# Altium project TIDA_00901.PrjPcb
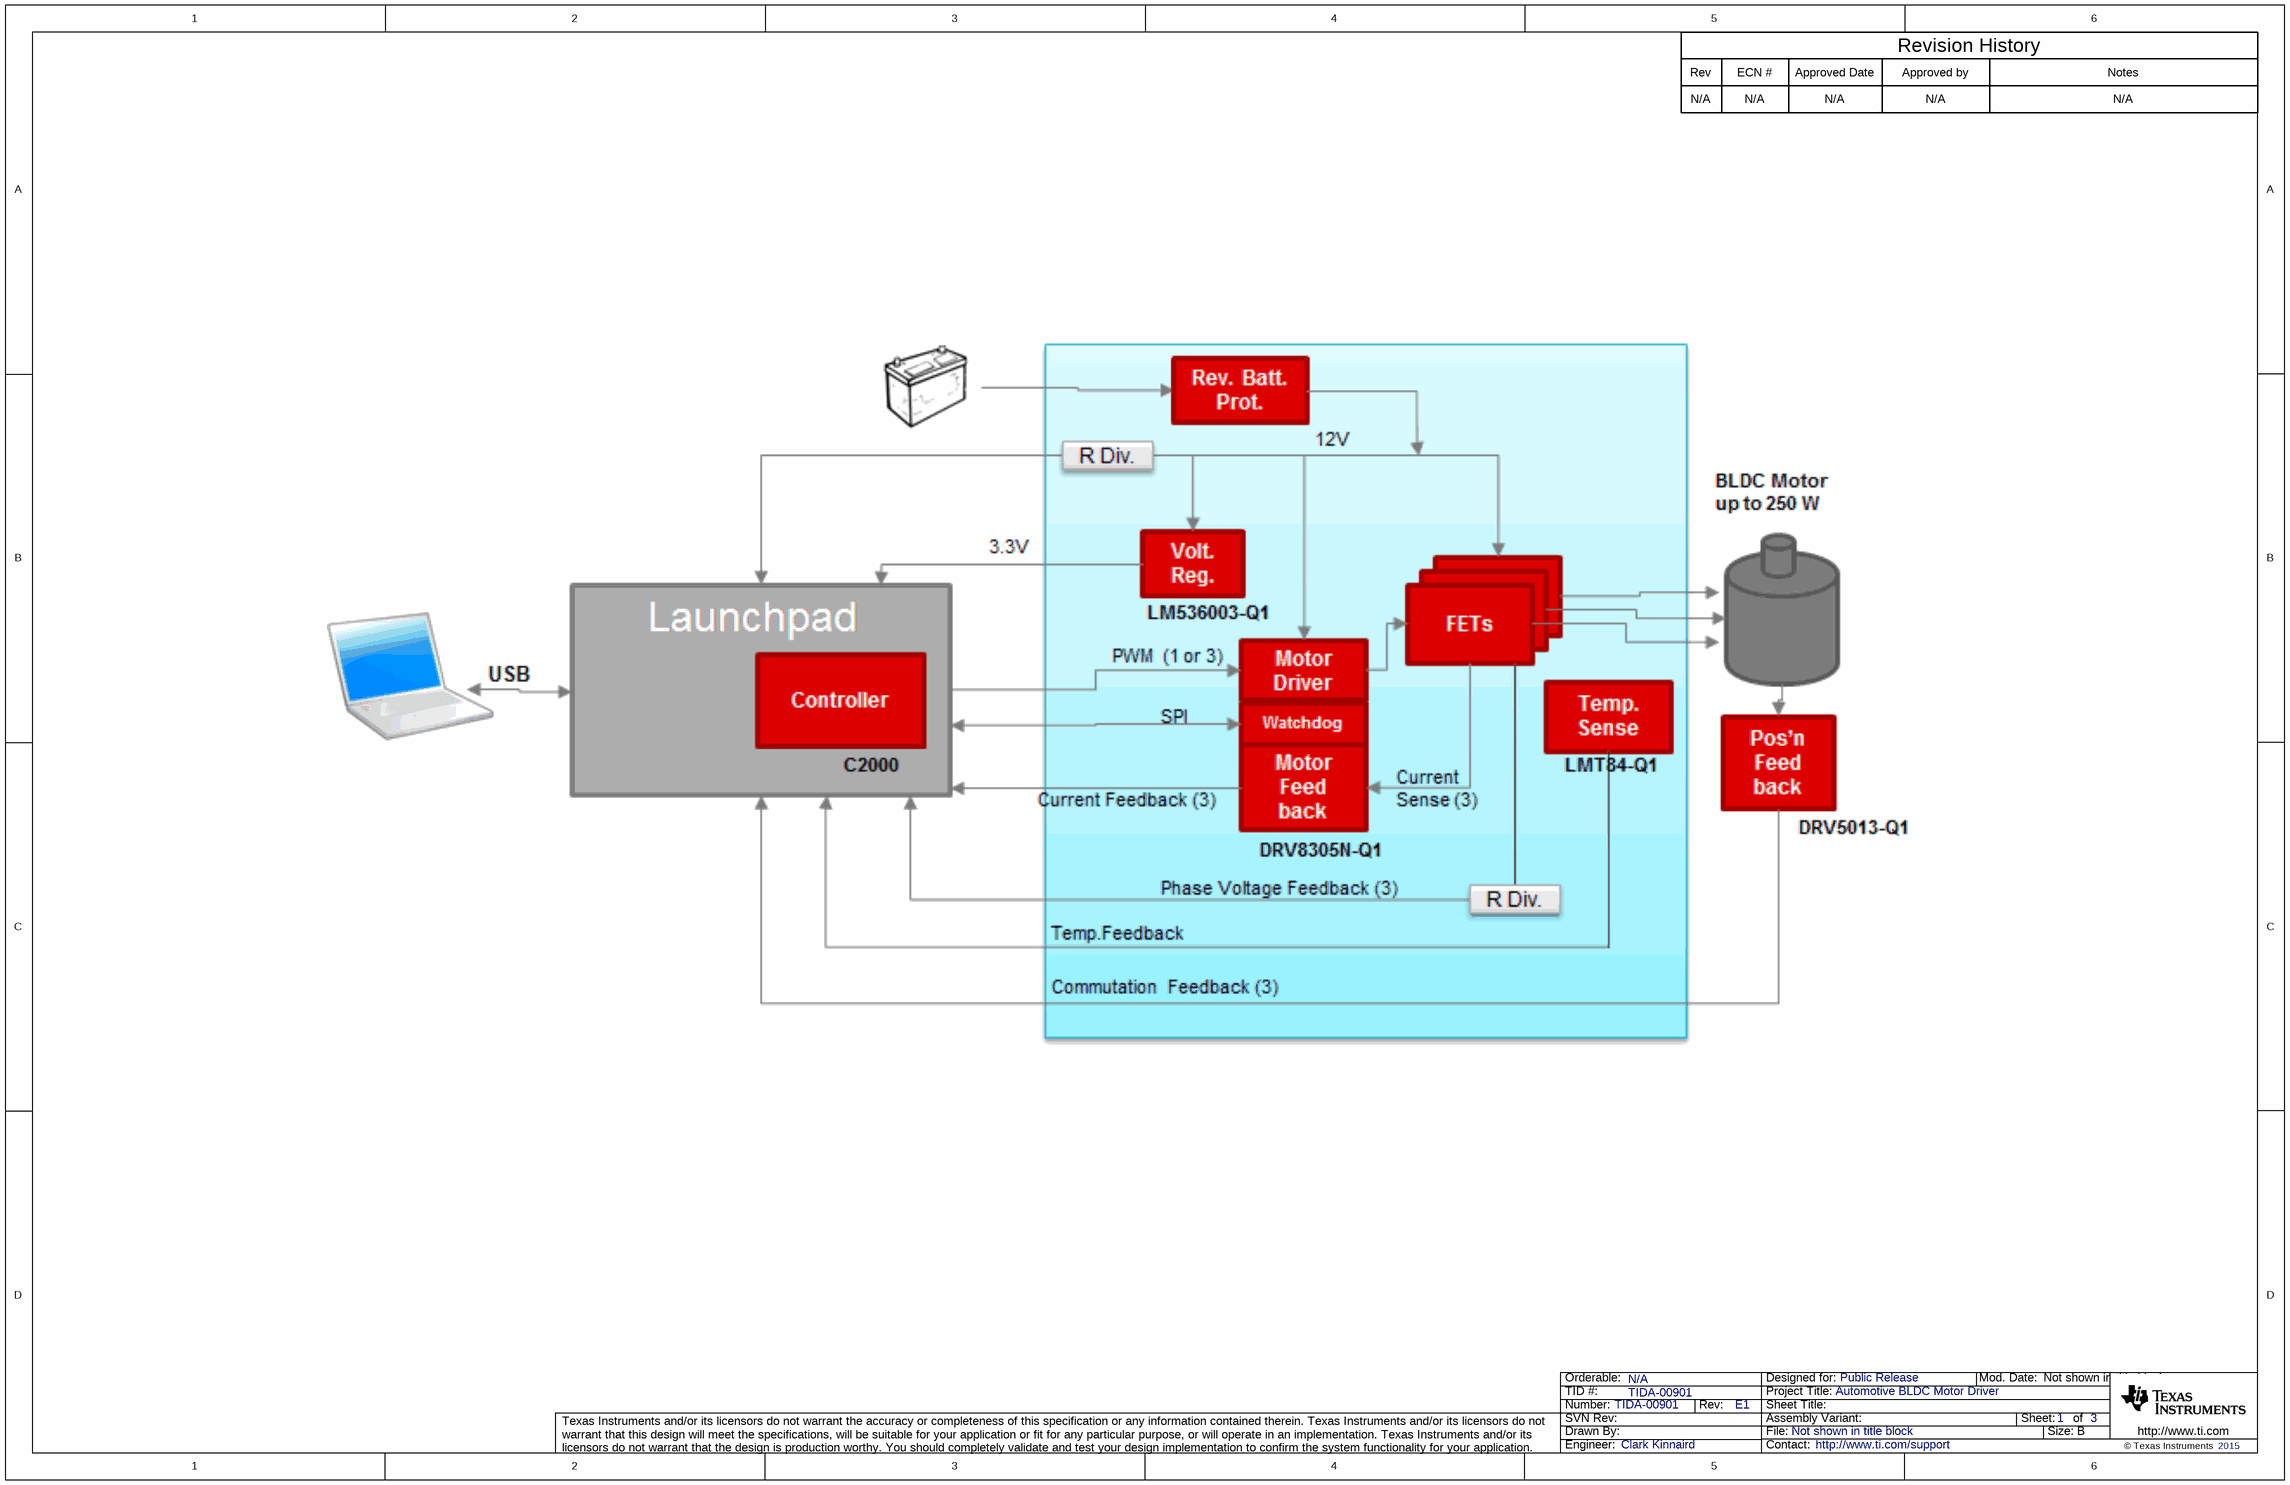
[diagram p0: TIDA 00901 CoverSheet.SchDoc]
CopyrightYear: 2015; EVM_Orderable: N/A; PCB_Layout: Krypton Solutions LLC; PCB_Rev: E1; PRJ_Customer: Public Release; PRJ_Engineer: Clark Kinnaird; PRJ_Number: TIDA-00901; PRJ_Title: Automotive BLDC Motor Driver; SCH_Rev: E1; TechSupport: http://www.ti.com/support; TID: TIDA-00901
3 sheets, 114 parts. Net scope: global (net labels, ports and power ports of the same name join across sheets).
Board file: TIDA_00901.PcbDoc
Sheets:
  TIDA 00901 CoverSheet.SchDoc
  TIDA 00901 Schematic 2.SchDoc
  TID_Hardware.SchDoc

## Sheet TIDA 00901 CoverSheet.SchDoc
size 431 x 279 mm; Date: Not shown in title block; ApprovedBy: Not shown in title block; CheckedBy: Not shown in title block; Author: Not shown in title block; CompanyName: Not shown in title block; Engineer: Not shown in title block; Organization: Not shown in title block; Address1: Not shown in title block; Address2: Not shown in title block; Address3: Not shown in title block; Address4: Not shown in title block; DocumentNumber: 1; Revision: Use project parameter SCH_Rev; SheetNumber: 1; SheetTotal: 3; PageSetup: Record=PageOptions¦CenterHorizontal=True¦CenterVertical=True¦PrintScale=1.00¦XCorrection=1.00¦YCorrection=1.00¦PrintKind=0¦BorderSize=5000000¦LeftOffset=0¦BottomOffset=0¦Orientation=2¦PaperLength=1000¦PaperWidth=1000¦Scale=100¦PaperSource=15¦PrintQuality=600¦MediaType=1¦DitherType=10¦PaperKind=Letter¦PrintScaleMode=1

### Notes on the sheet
- Rev
- N/A
- ECN #
- Approved Date
- Approved by
- Revision History
- Notes

## Sheet TIDA 00901 Schematic 2.SchDoc
size 431 x 279 mm; Date: Not shown in title block; ApprovedBy: Not shown in title block; CheckedBy: Not shown in title block; Author: Not shown in title block; CompanyName: Not shown in title block; Engineer: Not shown in title block; Organization: Not shown in title block; Address1: Not shown in title block; Address2: Not shown in title block; Address3: Not shown in title block; Address4: Not shown in title block; DocumentNumber: 1; Revision: Use project parameter SCH_Rev; SheetNumber: 2; SheetTotal: 2; PageSetup: Record=PageOptions¦CenterHorizontal=True¦CenterVertical=True¦PrintScale=0.96¦XCorrection=1.00¦YCorrection=1.00¦PrintKind=0¦BorderSize=5000000¦LeftOffset=0¦BottomOffset=0¦Orientation=2¦PaperLength=4318¦PaperWidth=2794¦Scale=100¦PaperSource=15¦PrintQuality=-3¦MediaType=1¦DitherType=10¦PrintScaleMode=1¦PaperKind=11x17¦PaperIndex=17
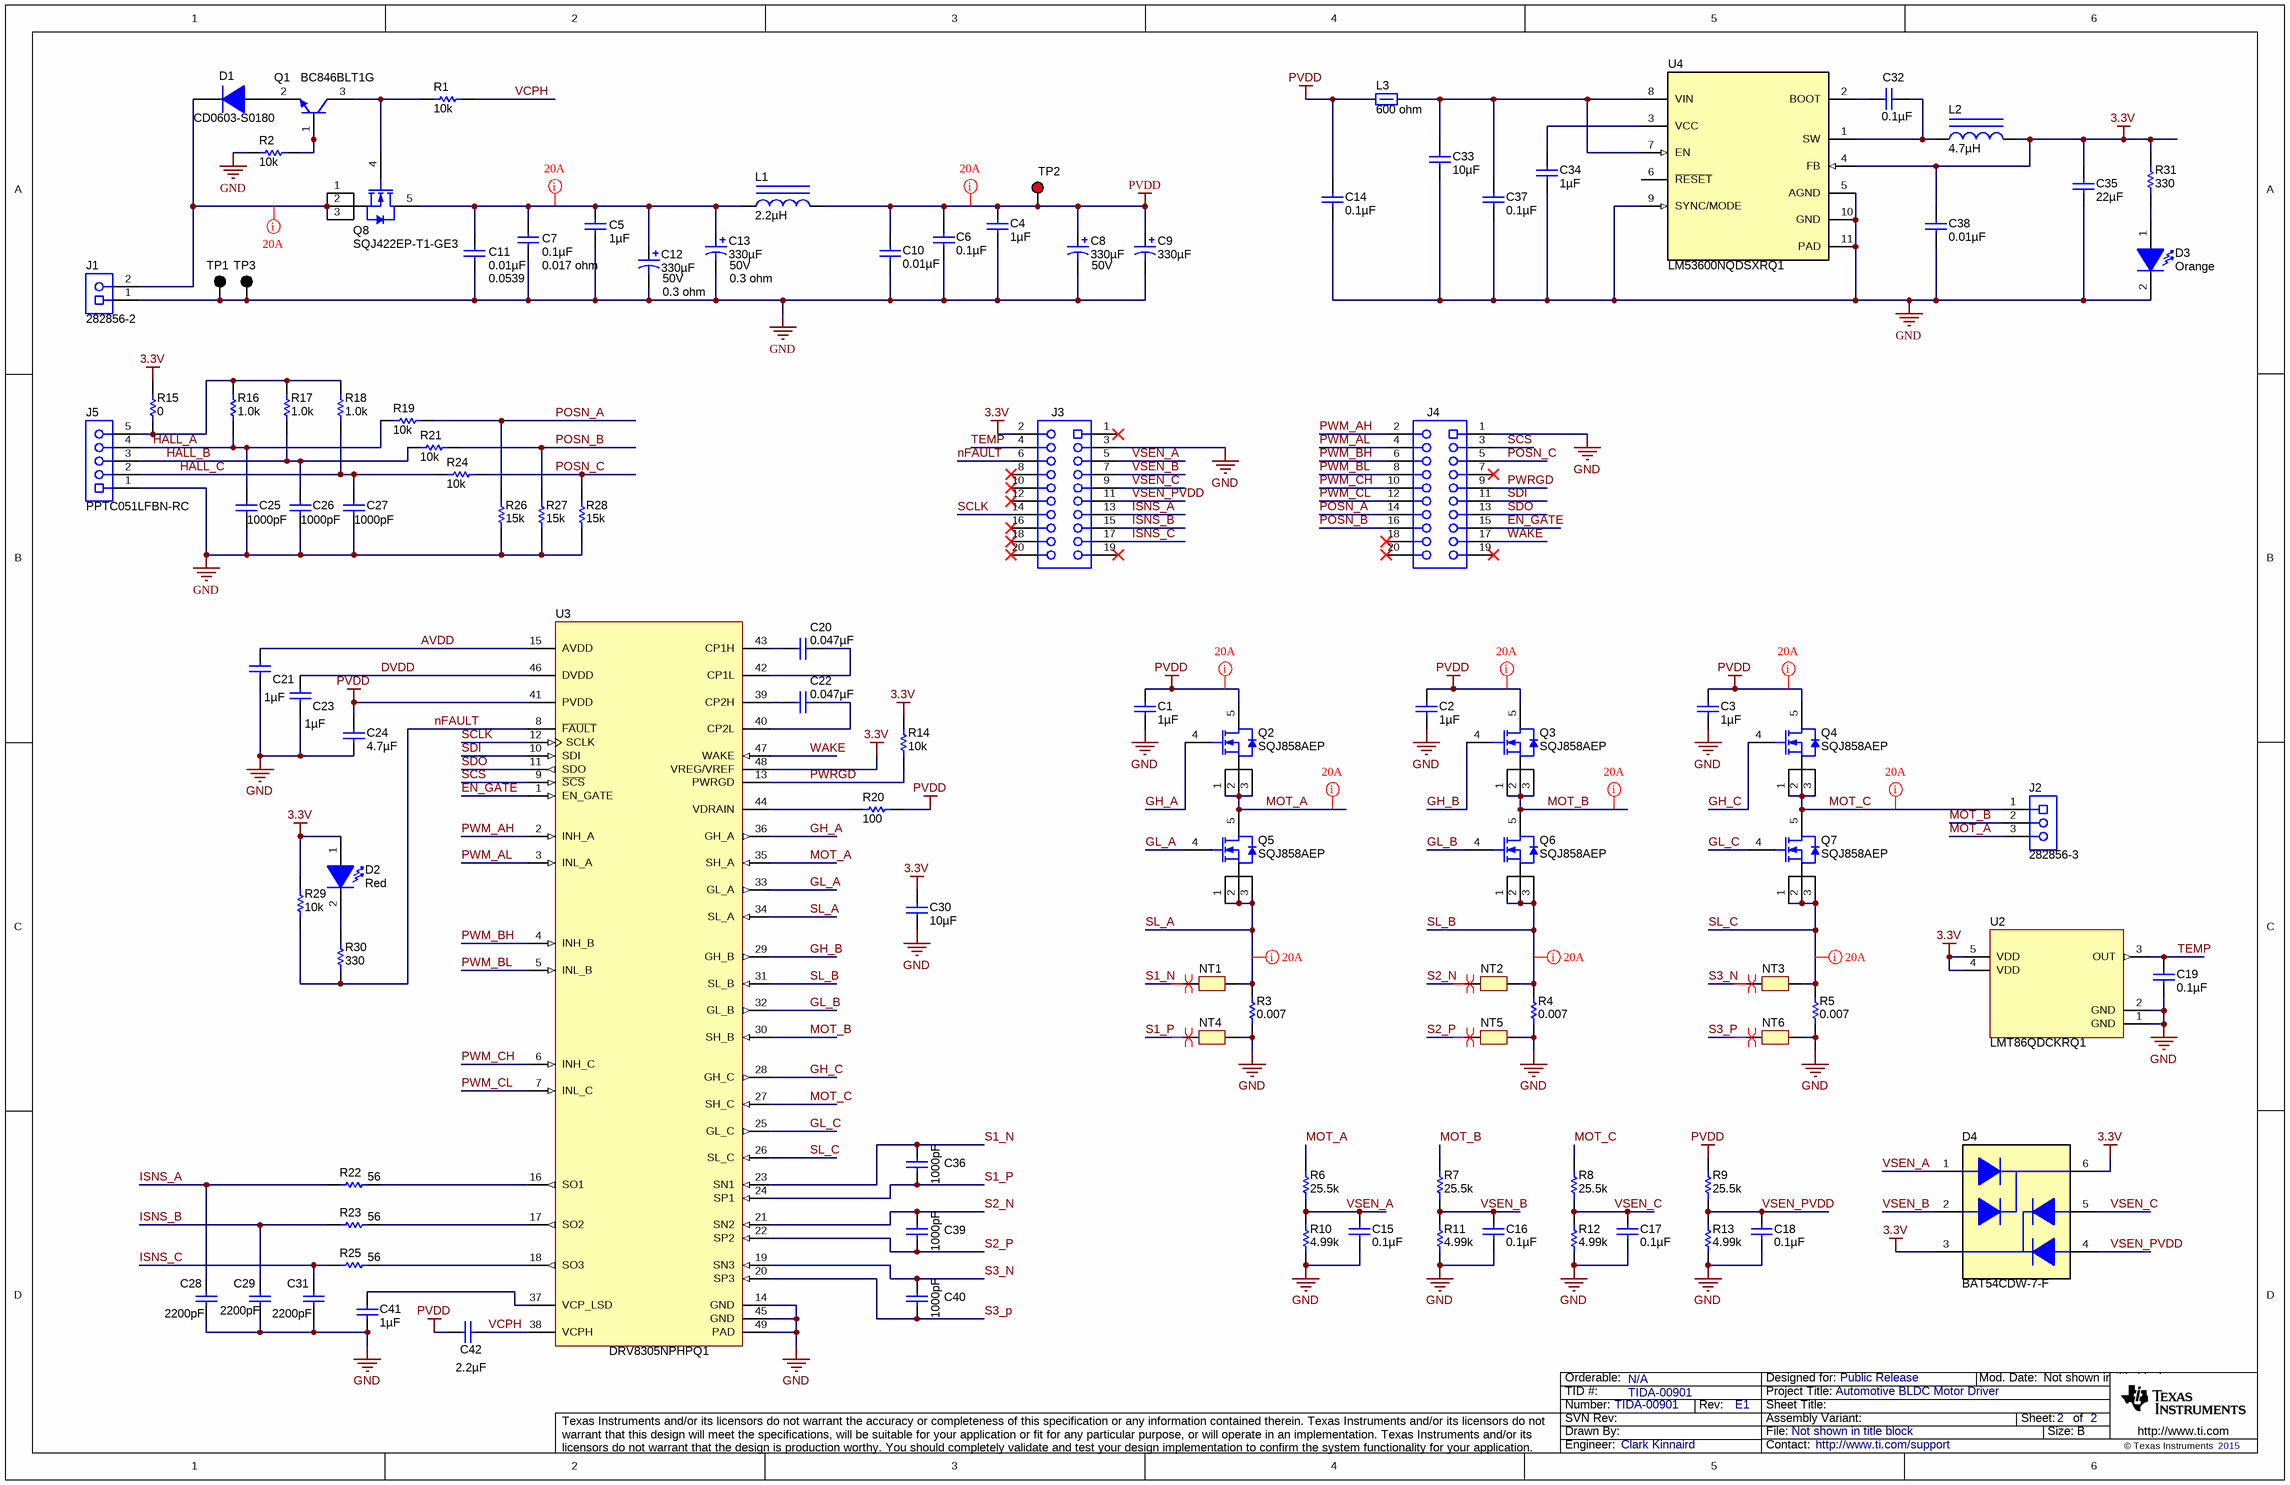
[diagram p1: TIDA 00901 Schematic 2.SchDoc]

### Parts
C1  ValueDisplayed: 1µF  [0603L]  (hidden comment: UMK107AB7105KA-T)
C2  ValueDisplayed: 1µF  [0603L]  (hidden comment: UMK107AB7105KA-T)
C3  ValueDisplayed: 1µF  [0603L]  (hidden comment: UMK107AB7105KA-T)
C4  ValueDisplayed: 1µF  [0805L]  (hidden comment: GRM21BR71H105KA12L)
C5  ValueDisplayed: 1µF  [0805L]  (hidden comment: GRM21BR71H105KA12L)
C6  ValueDisplayed: 0.1µF  [0603L]  (hidden comment: C1608X7R1H104K)
C7  ValueDisplayed: 0.1µF  Value1: 0.017 ohm  [0603L]  (hidden comment: C1608X7R1H104K)
C8  ValueDisplayed: 330µF  Value2: 50V  [SM_RADIAL_G]  (hidden comment: EEE-FT1H331AP)
C9  ValueDisplayed: 330µF  [SM_RADIAL_G]  (hidden comment: EEE-FT1H331AP)
C10  ValueDisplayed: 0.01µF  [0603L]  (hidden comment: C1608X7R1H103K)
C11  ValueDisplayed: 0.01µF  ESR_Ohm: 0.0539  [0603L]  (hidden comment: C1608X7R1H103K)
C12  ValueDisplayed: 330µF  Value1: 0.3 ohm  Value2: 50V  [SM_RADIAL_G]  (hidden comment: EEE-FT1H331AP)
C13  ValueDisplayed: 330µF  Value1: 0.3 ohm  Value2: 50V  [SM_RADIAL_G]  (hidden comment: EEE-FT1H331AP)
C14  ValueDisplayed: 0.1µF  [0603]  (hidden comment: GRM188R71H104KA93D)
C15  ValueDisplayed: 0.1µF  [0603L]  (hidden comment: C0603C104J4RACTU)
C16  ValueDisplayed: 0.1µF  [0603L]  (hidden comment: C0603C104J4RACTU)
C17  ValueDisplayed: 0.1µF  [0603L]  (hidden comment: C0603C104J4RACTU)
C18  ValueDisplayed: 0.1µF  [0603L]  (hidden comment: C0603C104J4RACTU)
C19  ValueDisplayed: 0.1µF  [0402]  (hidden comment: C0402C104K4RACAUTO)
C20  ValueDisplayed: 0.047µF  [0603L]  (hidden comment: C0603C473K1RACTU)
C21  ValueDisplayed: 1µF  [0603L]  (hidden comment: C1608X7R1C105K)
C22  ValueDisplayed: 0.047µF  [0603L]  (hidden comment: C0603C473K1RACTU)
C23  ValueDisplayed: 1µF  [0603L]  (hidden comment: C1608X7R1C105K)
C24  ValueDisplayed: 4.7µF  [1206L]  (hidden comment: GRM31CR71H475KA12L)
C25  ValueDisplayed: 1000pF  [0603L]  (hidden comment: GRM188R71C102KA01D)
C26  ValueDisplayed: 1000pF  [0603L]  (hidden comment: GRM188R71C102KA01D)
C27  ValueDisplayed: 1000pF  [0603L]  (hidden comment: GRM188R71C102KA01D)
C28  ValueDisplayed: 2200pF  [0603L]  (hidden comment: GRM188R71C222KA01D)
C29  ValueDisplayed: 2200pF  [0603L]  (hidden comment: GRM188R71C222KA01D)
C30  ValueDisplayed: 10µF  [0805_HV]  (hidden comment: C2012X7R1A106M125AC)
C31  ValueDisplayed: 2200pF  [0603L]  (hidden comment: GRM188R71C222KA01D)
C32  ValueDisplayed: 0.1µF  [0603]  (hidden comment: GRM188R71H104KA93D)
C33  ValueDisplayed: 10µF  [1210_280]  (hidden comment: C3225X7R1H106M250AC)
C34  ValueDisplayed: 1µF  [0603]  (hidden comment: GRM188R71C105KA12D)
C35  ValueDisplayed: 22µF  [1206]  (hidden comment: GRM31CR71A226KE15L)
C36  ValueDisplayed: 1000pF  [0603L]  (hidden comment: GRM188R71C102KA01D)
C37  ValueDisplayed: 0.1µF  [0603]  (hidden comment: GRM188R71H104KA93D)
C38  ValueDisplayed: 0.01µF  [0201]  (hidden comment: GRM033R71A103KA01D)
C39  ValueDisplayed: 1000pF  [0603L]  (hidden comment: GRM188R71C102KA01D)
C40  ValueDisplayed: 1000pF  [0603L]  (hidden comment: GRM188R71C102KA01D)
C41  ValueDisplayed: 1µF  [0603L]  (hidden comment: C1608X7R1C105K)
C42  ValueDisplayed: 2.2µF  [1210L]  (hidden comment: GRM32ER72A225KA35L)
D1  CD0603-S0180  [Diode_0603]
D2  value Red  [LED_LTST-C170]  (hidden comment: LTST-C170KRKT)
D3  value Orange  [LED_LTST-C190]  (hidden comment: LTST-C190KFKT)
D4  BAT54CDW-7-F  [SOT-363]
J1  282856-2  [TE_282856-2]
J2  282856-3  [TE_282856-3]
J3  CRD-081413-A-G  [Major_CRD-081413-A-x]  (value not drawn)
J4  CRD-081413-A-G  [Major_CRD-081413-A-x]  (value not drawn)
J5  PPTC051LFBN-RC  [Sullins_PPTC051LFBN-RC]
L1  ValueDisplayed: 2.2µH  [XAL1010]  (hidden comment: XAL1010-222MEB)
L2  ValueDisplayed: 4.7µH  [SPM3012]  (hidden comment: SPM3012T-4R7M)
L3  value 600 ohm  [0402]  (hidden comment: BLM15AX601SN1D)
NT1  Net-Tie  [Net-Tie_10mil]  (value not drawn)  (net tie, no BOM)
NT2  Net-Tie  [Net-Tie_10mil]  (value not drawn)  (net tie, no BOM)
NT3  Net-Tie  [Net-Tie_10mil]  (value not drawn)  (net tie, no BOM)
NT4  Net-Tie  [Net-Tie_10mil]  (value not drawn)  (net tie, no BOM)
NT5  Net-Tie  [Net-Tie_10mil]  (value not drawn)  (net tie, no BOM)
NT6  Net-Tie  [Net-Tie_10mil]  (value not drawn)  (net tie, no BOM)
Q1  BC846BLT1G  [SOT-23]
Q2  SQJ858AEP  [PowerPAK_SO-8L]
Q3  SQJ858AEP  [PowerPAK_SO-8L]
Q4  SQJ858AEP  [PowerPAK_SO-8L]
Q5  SQJ858AEP  [PowerPAK_SO-8L]
Q6  SQJ858AEP  [PowerPAK_SO-8L]
Q7  SQJ858AEP  [PowerPAK_SO-8L]
Q8  SQJ422EP-T1-GE3  [PowerPAK_SO-8L]
R1  ValueDisplayed: 10k  [0402]  (hidden comment: CRCW040210K0JNED)
R2  ValueDisplayed: 10k  [0402]  (hidden comment: CRCW040210K0JNED)
R3  ValueDisplayed: 0.007  [2512L]  (hidden comment: CRE2512-FZ-R007E-3)
R4  ValueDisplayed: 0.007  [2512L]  (hidden comment: CRE2512-FZ-R007E-3)
R5  ValueDisplayed: 0.007  [2512L]  (hidden comment: CRE2512-FZ-R007E-3)
R6  ValueDisplayed: 25.5k  [0402]  (hidden comment: CRCW040225K5FKED)
R7  ValueDisplayed: 25.5k  [0402]  (hidden comment: CRCW040225K5FKED)
R8  ValueDisplayed: 25.5k  [0402]  (hidden comment: CRCW040225K5FKED)
R9  ValueDisplayed: 25.5k  [0402]  (hidden comment: CRCW040225K5FKED)
R10  ValueDisplayed: 4.99k  [0402]  (hidden comment: CRCW04024K99FKED)
R11  ValueDisplayed: 4.99k  [0402]  (hidden comment: CRCW04024K99FKED)
R12  ValueDisplayed: 4.99k  [0402]  (hidden comment: CRCW04024K99FKED)
R13  ValueDisplayed: 4.99k  [0402]  (hidden comment: CRCW04024K99FKED)
R14  ValueDisplayed: 10k  [0402]  (hidden comment: CRCW040210K0JNED)
R15  ValueDisplayed: 0  [0402]  (hidden comment: ERJ-2GE0R00X)
R16  ValueDisplayed: 1.0k  [0402]  (hidden comment: CRCW04021K00JNED)
R17  ValueDisplayed: 1.0k  [0402]  (hidden comment: CRCW04021K00JNED)
R18  ValueDisplayed: 1.0k  [0402]  (hidden comment: CRCW04021K00JNED)
R19  ValueDisplayed: 10k  [0402]  (hidden comment: CRCW040210K0JNED)
R20  ValueDisplayed: 100  [0402]  (hidden comment: CRCW0402100RFKED)
R21  ValueDisplayed: 10k  [0402]  (hidden comment: CRCW040210K0JNED)
R22  ValueDisplayed: 56  [0402]  (hidden comment: CRCW040256R0JNED)
R23  ValueDisplayed: 56  [0402]  (hidden comment: CRCW040256R0JNED)
R24  ValueDisplayed: 10k  [0402]  (hidden comment: CRCW040210K0JNED)
R25  ValueDisplayed: 56  [0402]  (hidden comment: CRCW040256R0JNED)
R26  ValueDisplayed: 15k  [0402]  (hidden comment: CRCW040215K0JNED)
R27  ValueDisplayed: 15k  [0402]  (hidden comment: CRCW040215K0JNED)
R28  ValueDisplayed: 15k  [0402]  (hidden comment: CRCW040215K0JNED)
R29  ValueDisplayed: 10k  [0402]  (hidden comment: CRCW040210K0JNED)
R30  ValueDisplayed: 330  [0402]  (hidden comment: CRCW0402330RJNED)
R31  ValueDisplayed: 330  [0402]  (hidden comment: CRCW0402330RJNED)
TP1  5006  [Keystone5006]  (value not drawn)
TP2  5005  [Keystone5005]  (value not drawn)
TP3  5006  [Keystone5006]  (value not drawn)
U2  LMT86QDCKRQ1  [DCK0005A_N]
U3  DRV8305NPHPQ1  [PHP0048G_L]
U4  LM53600NQDSXRQ1  [DSX0010A]

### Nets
3.3V: C30.1 C35.1 C38.1 D2.1(A) D4.3(C2) D4.6(C1) J3.2 L2.2 R14.2 R15.2 R29.2 R31.2 U2.4(VDD) U2.5(VDD) U3.48(VREG/VREF) U4.4(FB)
GND: C1.2 C2.2 C3.2 C4.2 C5.2 C6.2 C7.2 C8.2(-) C9.2(-) C10.2 C11.2 C12.2(-) C13.2(-) C14.2 C15.2 C16.2 C17.2 C18.2 C19.2 C21.1 C23.1 C24.1 C25.2 C26.2 C27.2 C28.2 C29.2 C30.2 C31.2 C33.2 C34.2 C35.2 C37.2 C38.2 C41.2 D3.2(K) J1.1 J3.3 J4.1 J5.1 NT4.2 NT5.2 NT6.2 R2.2 R3.1 R4.1 R5.1 R10.1 R11.1 R12.1 R13.1 R26.1 R27.1 R28.1 TP1.1 TP3.1 U2.1(GND) U2.2(GND) U3.14(GND) U3.45(GND) U3.49(PAD) U4.5(AGND) U4.9(SYNC/MODE) U4.10(GND) U4.11(PAD)
PVDD: C1.1 C2.1 C3.1 C4.1 C6.1 C8.1(+) C9.1(+) C10.1 C14.1 C24.2 C42.2 L1.2 L3.1 Q2.5(D) Q3.5(D) Q4.5(D) R9.2 R20.2 TP2.1 U3.41(PVDD)
AVDD: C21.2 U3.15(AVDD)
DVDD: C23.2 U3.46(DVDD)
EN_GATE: J4.15 U3.1(EN_GATE)
GH_A: Q2.4(G) U3.36(GH_A)
GH_B: Q3.4(G) U3.29(GH_B)
GH_C: Q4.4(G) U3.28(GH_C)
GL_A: Q5.4(G) U3.33(GL_A)
GL_B: Q6.4(G) U3.32(GL_B)
GL_C: Q7.4(G) U3.25(GL_C)
HALL_A: C25.1 J5.4 R16.1 R19.1
HALL_B: C26.1 J5.3 R17.1 R21.1
HALL_C: C27.1 J5.2 R18.1 R24.1
ISNS_A: C28.1 J3.13 R22.1
ISNS_B: C29.1 J3.15 R23.1
ISNS_C: C31.1 J3.17 R25.1
MOT_A: J2.3 Q2.1(S) Q2.2(S) Q2.3(S) Q5.5(D) R6.2 U3.35(SH_A)
MOT_B: J2.2 Q3.1(S) Q3.2(S) Q3.3(S) Q6.5(D) R7.2 U3.30(SH_B)
MOT_C: J2.1 Q4.1(S) Q4.2(S) Q4.3(S) Q7.5(D) R8.2 U3.27(SH_C)
nFAULT: J3.6 R29.1 R30.1 U3.8(~{FAULT})
POSN_A: J4.14 R19.2 R26.2
POSN_B: J4.16 R21.2 R27.2
POSN_C: J4.5 R24.2 R28.2
PWM_AH: J4.2 U3.2(INH_A)
PWM_AL: J4.4 U3.3(INL_A)
PWM_BH: J4.6 U3.4(INH_B)
PWM_BL: J4.8 U3.5(INL_B)
PWM_CH: J4.10 U3.6(INH_C)
PWM_CL: J4.12 U3.7(INL_C)
PWRGD: J4.9 R14.1 U3.13(PWRGD)
S1_N: C36.1 NT1.1 U3.23(SN1)
S1_P: C36.2 NT4.1 U3.24(SP1)
S2_N: C39.1 NT2.1 U3.21(SN2)
S2_P: C39.2 NT5.1 U3.22(SP2)
S3_N: C40.1 NT3.1 U3.19(SN3)
S3_p: C40.2 NT6.1 U3.20(SP3)
SCLK: J3.14 U3.12(SCLK)
SCS: J4.3 U3.9(~{SCS})
SDI: J4.11 U3.10(SDI)
SDO: J4.13 U3.11(SDO)
SL_A: NT1.2 Q5.1(S) Q5.2(S) Q5.3(S) R3.2 U3.34(SL_A)
SL_B: NT2.2 Q6.1(S) Q6.2(S) Q6.3(S) R4.2 U3.31(SL_B)
SL_C: NT3.2 Q7.1(S) Q7.2(S) Q7.3(S) R5.2 U3.26(SL_C)
TEMP: C19.1 J3.4 U2.3(OUT)
VCPH: C42.1 R1.1 U3.38(VCPH)
VSEN_A: C15.1 D4.1(A1) J3.5 R6.1 R10.2
VSEN_B: C16.1 D4.2(A1) J3.7 R7.1 R11.2
VSEN_C: C17.1 D4.5(A2) J3.9 R8.1 R12.2
VSEN_PVDD: C18.1 D4.4(A2) J3.11 R9.1 R13.2
WAKE: J4.17 U3.47(WAKE)
NetC5_1: C5.1 C7.1 C11.1 C12.1(+) C13.1(+) L1.1 Q8.5(D)
NetC20_1: C20.1 U3.43(CP1H)
NetC20_2: C20.2 U3.42(CP1L)
NetC22_1: C22.1 U3.39(CP2H)
NetC22_2: C22.2 U3.40(CP2L)
NetC32_1: C32.1 U4.2(BOOT)
NetC32_2: C32.2 L2.1 U4.1(SW)
NetC33_1: C33.1 C37.1 L3.2 U4.7(EN) U4.8(VIN)
NetC34_1: C34.1 U4.3(VCC)
NetC41_1: C41.1 U3.37(VCP_LSD)
NetD1_1: D1.1(K) J1.2 Q8.1(S) Q8.2(S) Q8.3(S)
NetD1_2: D1.2(A) Q1.2(E)
NetD2_2: D2.2(K) R30.2
NetD3_1: D3.1(A) R31.1
NetJ5_5: J5.5 R15.1 R16.2 R17.2 R18.2
NetQ1_1: Q1.1(B) R2.1
NetQ1_3: Q1.3(C) Q8.4(G) R1.2
NetR20_1: R20.1 U3.44(VDRAIN)
NetR22_2: R22.2 U3.16(SO1)
NetR23_2: R23.2 U3.17(SO2)
NetR25_2: R25.2 U3.18(SO3)

Not connected (* = marked no-connect by the designer): J3 1* 8* 10* 12* 16* 18* 19* 20*; J4 7* 18* 19* 20*; U4 6(~{RESET})

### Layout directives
rule Undefined: MOT_A, MOT_B, MOT_C, NetC5_1, NetD1_1, PVDD, SL_A, SL_B, SL_C
differential pair: S1_N, S1_P, S2_N, S2_P, S3_N, S3_p

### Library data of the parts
C1-C3 = UMK107AB7105KA-T: CAP, CERM, 1 µF, 50 V, +/- 10%, X7R, 0603; Manufacturer: Taiyo Yuden; Polarized: N; CompType: Capacitor; Value: 1uF; U/M: EA; Cap_F: 0.000001; Tolerance_%: 10; Value1: Unknown; VDC_V: 50; Value2: 50V; TaMin_C: -55; TaMax_C: 125; Cap_Case: 0603
C4 C5 = GRM21BR71H105KA12L: CAP, CERM, 1uF, 50V, +/-10%, X7R, 0805; Manufacturer: MuRata; Polarized: N; CompType: Capacitor; U/M: EA; Cap_F: 0.000001; Tolerance_%: 10; Value1: Unknown; VDC_V: 50; TaMin_C: -55; TaMax_C: 125; Cap_Case: 0805
C6 = C1608X7R1H104K: CAP, CERM, 0.1uF, 50V, +/-10%, X7R, 0603; Manufacturer: TDK; Polarized: N; CompType: Capacitor; U/M: EA; Cap_F: 0.0000001; Tolerance_%: 10; ESR_Ohm: 0.017; Value1: 0.017 ohm; VDC_V: 50; TaMin_C: -55; TaMax_C: 125; Cap_Case: 0603
C7 = C1608X7R1H104K: CAP, CERM, 0.1uF, 50V, +/-10%, X7R, 0603; Manufacturer: TDK; Polarized: N; CompType: Capacitor; U/M: EA; Cap_F: 0.0000001; Tolerance_%: 10; ESR_Ohm: 0.017; VDC_V: 50; TaMin_C: -55; TaMax_C: 125; Cap_Case: 0603
C8 = EEE-FC1H221P: CAP, AL, 330 µF, 50 V, +/- 20%, 0.3 ohm, SMD; Manufacturer: Panasonic; Polarized: Y; CompType: Capacitor; Value: 330uF; U/M: EA; Cap_F: 0.00033; Tolerance_%: 20; Value1: 0.3 ohm; VDC_V: 50; ESR_ohm: 0.3; IRMS_A: 0.5; TaMin_C: -40; TaMax_C: 105; Cap_Case: G
C9 = EEE-FC1H221P: CAP, AL, 330 µF, 50 V, +/- 20%, 0.3 ohm, SMD; Manufacturer: Panasonic; Polarized: Y; CompType: Capacitor; Value: 330uF; U/M: EA; Cap_F: 0.00033; Tolerance_%: 20; Value1: 0.3 ohm; VDC_V: 50; Value2: 50V; ESR_ohm: 0.3; IRMS_A: 0.5; TaMin_C: -40; TaMax_C: 105; Cap_Case: G
C10 = C1608X7R1H103K: CAP, CERM, 0.01uF, 50V, +/-10%, X7R, 0603; Manufacturer: TDK; Polarized: N; CompType: Capacitor; U/M: EA; Cap_F: 0.00000001; Tolerance_%: 10; ESR_Ohm: 0.0539; Value1: 0.0539 ohm; VDC_V: 50; TaMin_C: -55; TaMax_C: 125; Cap_Case: 0603
C11 = C1608X7R1H103K: CAP, CERM, 0.01uF, 50V, +/-10%, X7R, 0603; Manufacturer: TDK; Polarized: N; CompType: Capacitor; U/M: EA; Cap_F: 0.00000001; Tolerance_%: 10; Value1: 0.0539 ohm; VDC_V: 50; TaMin_C: -55; TaMax_C: 125; Cap_Case: 0603
C12 C13 = EEE-FC1H221P: CAP, AL, 330 µF, 50 V, +/- 20%, 0.3 ohm, SMD; Manufacturer: Panasonic; Polarized: Y; CompType: Capacitor; Value: 330uF; U/M: EA; Cap_F: 0.00033; Tolerance_%: 20; VDC_V: 50; ESR_ohm: 0.3; IRMS_A: 0.5; TaMin_C: -40; TaMax_C: 105; Cap_Case: G
C14 C32 C37 = GRM188R71H104KA93D: CAP, CERM, 0.1 µF, 50 V, +/- 10%, X7R, 0603; Manufacturer: MuRata; Polarized: N; CompType: Capacitor; Value: 0.1uF; U/M: EA; Cap_F: 0.0000001; Tolerance_%: 10; Value1: Unknown; VDC_V: 50; Value2: 50V; TaMin_C: -55; TaMax_C: 125; AEC Category: Q200
C15-C18 = C0603C104J4RACTU: CAP, CERM, 0.1 µF, 16 V, +/- 5%, X7R, 0603; Manufacturer: Kemet; Polarized: N; CompType: Capacitor; Value: 0.1uF; U/M: EA; Cap_F: 0.0000001; Tolerance_%: 5; Value1: Unknown; VDC_V: 16; Value2: 16V; TaMin_C: -55; TaMax_C: 125; Cap_Case: 0603
C19 = C0402C104K4RACAUTO: CAP, CERM, 0.1 µF, 16 V, +/- 10%, X7R, AEC-Q200 Grade 1, 0402; Manufacturer: Kemet; Polarized: N; CompType: Capacitor; Value: 0.1uF; U/M: EA; Cap_F: 0.0000001; Tolerance_%: 10; Value1: Unknown; VDC_V: 16; Value2: 16V; TaMin_C: -55; TaMax_C: 125; AEC Category: Q200; AEC Qualified: Y; AEC Grade: 1
C20 C22 = GRM188R72A104KA35D: CAP, CERM, 0.047uF, 100V, +/-10%, X7R, 0603; Manufacturer: Kemet; Polarized: N; CompType: Capacitor; U/M: EA; Cap_F: 0.000000047; Tolerance_%: 10; Value1: Unknown; VDC_V: 100; TaMin_C: -55; TaMax_C: 125; Cap_Case: 0603
C21 C23 C41 = C1608X7R1C105K: CAP, CERM, 1 µF, 16 V, +/- 10%, X7R, 0603; Manufacturer: TDK; Polarized: N; CompType: Capacitor; Value: 1uF; U/M: EA; Cap_F: 0.000001; Tolerance_%: 10; ESR_ohm: 0.0057; Value1: 0.0057 ohm; VDC_V: 16; Value2: 16V; TaMin_C: -55; TaMax_C: 125; Cap_Case: 0603
C24 = GRM31CR71H475KA12L: CAP, CERM, 4.7 µF, 50 V, +/- 10%, X7R, 1206; Manufacturer: MuRata; Polarized: N; CompType: Capacitor; Value: 4.7uF; U/M: EA; Cap_F: 0.0000047; Tolerance_%: 10; Value1: Unknown; VDC_V: 50; Value2: 50V; TaMin_C: -55; TaMax_C: 125; Cap_Case: 2220
C25-C27 C36 C39 C40 = GRM188R71C102KA01D: CAP, CERM, 1000pF, 16V, +/-10%, X7R, 0603; Manufacturer: MuRata; Polarized: N; CompType: Capacitor; U/M: EA; Cap_F: 0.000000001; Tolerance_%: 10; Value1: Unknown; VDC_V: 16; TaMin_C: -55; TaMax_C: 125; Cap_Case: 0603
C28 C29 C31 = GRM188R71C222KA01D: CAP, CERM, 2200pF, 16V, +/-10%, X7R, 0603; Manufacturer: MuRata; Polarized: N; CompType: Capacitor; U/M: EA; Cap_F: 0.0000000022; Tolerance_%: 10; Value1: Unknown; VDC_V: 16; TaMin_C: -55; TaMax_C: 125; Cap_Case: 0603
C30 = C2012X7R1A106M125AC: CAP, CERM, 10 µF, 10 V, +/- 20%, X7R, 0805; Manufacturer: TDK; Polarized: N; CompType: Capacitor; Value: 10uF; U/M: EA; Cap_F: 0.00001; Tolerance_%: 20; Value1: Unknown; VDC_V: 10; Value2: 10V; TaMin_C: -55; TaMax_C: 125; Cap_Case: 0805; AEC Category: Q200
C33 = C3225X7R1H106M250AC: CAP, CERM, 10 µF, 50 V, +/- 20%, X7R, 1210; Manufacturer: TDK; Polarized: N; CompType: Capacitor; Value: 10uF; U/M: EA; Cap_F: 0.00001; Tolerance_%: 20; Value1: Unknown; VDC_V: 50; Value2: 50V; TaMin_C: -55; TaMax_C: 125; Cap_Case: 1210; AEC Category: Q200
C34 = GRM188R71C105KA12D: CAP, CERM, 1 µF, 16 V, +/- 10%, X7R, 0603; Manufacturer: MuRata; Polarized: N; CompType: Capacitor; Value: 1uF; U/M: EA; Cap_F: 0.000001; Tolerance_%: 10; ESR_ohm: 0.011; Value1: 0.011 ohm; VDC_V: 16; Value2: 16V; TaMin_C: -55; TaMax_C: 125; AEC Category: Q200
C35 = GRM31CR71A226KE15L: CAP, CERM, 22 µF, 10 V, +/- 10%, X7R, 1206; Manufacturer: MuRata; Polarized: N; CompType: Capacitor; Value: 22uF; U/M: EA; Cap_F: 0.000022; Tolerance_%: 10; Value1: Unknown; Value2: 10V; TaMin_C: -55; TaMax_C: 125; AEC Category: Q200
C38 = GRM033R71A103KA01D: CAP, CERM, 0.01 µF, 10 V, +/- 10%, X7R, 0201; Manufacturer: MuRata; Polarized: N; CompType: Capacitor; Value: 0.01uF; U/M: EA; Cap_F: 0.00000001; Tolerance_%: 10; Value1: Unknown; Value2: 10V; TaMin_C: -55; TaMax_C: 125; AEC Category: Q200
C42 = GRM32ER72A225KA35L: CAP, CERM, 2.2 µF, 100 V, +/- 10%, X7R, 1210; Manufacturer: MuRata; Polarized: N; CompType: Capacitor; Value: 2.2uF; U/M: EA; Cap_F: 0.0000022; Tolerance_%: 10; ESR_ohm: 0.007; Value1: 0.007 ohm; VDC_V: 100; Value2: 100V; IRMS_A: 4.4; TaMin_C: -55; TaMax_C: 125; Cap_Case: 1210
D1 = CD0603-S0180: Diode, Switching, 90V, 0.1A, 0603 Diode; Manufacturer: Bourns; U/M: EA; Vf_V: 1; Value2: 1V; Io_A: 0.1; Vr_V: 90; TJmax_C: 125
D2 = LTST-C170KRKT: LED, Red, SMD; Manufacturer: Lite-On; Type: AlInGaP; Vf_V: 2; Value2: 2V; Io_A: 20; Value1: W; U/M: EA
D3 = LTST-C190KFKT: LED, Orange, SMD; Manufacturer: Lite-On; Type: AlInGaP; Vf_V: 2; Value2: 2V; Io_A: 0.02; Power_TotalModule: 0.075; Value1: 0.075W; U/M: EA
D4 = BAT54CDW-7-F: Diode, Schottky, 30 V, 0.2 A, SOT-363; Manufacturer: Diodes Inc.; SymbolCreator: Altium; U/M: EA; Vf_V: 1; Value: 30V; Value1: 0.2A; Value2: 1V; Io_A: 0.2; Vr_V: 30; TJmax_C: 125; AEC Category: Q101; AEC Qualified: N
J1 = 282856-2: Therminal Block, 5 mm, 2-pole, Tin, TH; Manufacturer: TE Connectivity; SymbolCreator: a0412235; CompType: Terminal Block
J2 = 282856-3: Receptacle, 3x1, 5mm, R/A, TH; Manufacturer: TE Connectivity; SymbolCreator: a0412235; CompType: Terminal Block; Pitch_mm: 5; Gender: Female; Row_Count: 1; ContactFinish: Tin; Current_A: 24; Voltage_V: 300; Cert_UL: Y
J3 J4 = CRD-081413-A-G: Receptacle, 2.54 mm, 10x2, Gold, TH; Manufacturer: Major League Electronics; SymbolCreator: a0412235; U/M: EA
J5 = PPTC051LFBN-RC: Receptacle, 2.54 mm, 5x1, Tin, TH; Manufacturer: Sullins Connector Solutions; SymbolCreator: a0412235; U/M: EA
L1 = XAL1010-222MEB: Inductor, Shielded, Composite, 2.2 µH, 32 A, 0.00255 ohm, SMD; Manufacturer: Coilcraft; Value: 2.2uH; Ind_H: 2.2E-6; Imax_A: 32; Irms: 32A @ 40C rise; Isat: 34A @ 30% inductance drop; Value2: 32A; AEC Category: Q200
L2 = SPM3012T-4R7M: Inductor, Shielded, Ferrite, 4.7 µH, 1.5 A, 0.27 ohm, SMD; Manufacturer: TDK; Value: 4.7uH; Ind_H: 4.7E-6; Imax_A: 1.5; Irms: 1.5A @ 40C rise; Isat: 1.5A @ 30% inductance drop; DCR_ohm: 0.27; Value2: 1.5A; AEC Category: Q200
L3 = BLM15AX601SN1D: Ferrite Bead, 600 ohm @ 100 MHz, 0.5 A, 0402; Manufacturer: MuRata; Imax_A: 0.5; DCR_ohm: 0.34; Value1: 0.34 ohm; Value2: 0.5A; ZTyp@100MHz_Ohm: 600
NT1-NT6 = Net-Tie: Single point connection between nets.; SymbolCreator: codlsc
Q1 = BC846BLT1G, ON Semiconductor: Transistor, NPN, 65V, 0.1A, SOT-23; CompType: BJT; PNP: 0; NPN: 1; Vceo_V: 65; Vcesat1_V: 0.7; Value: 0.7V; IcRated_A: 0.1; HfeMax: 450; TaMin_C: -55; TaMax_C: 150; U/M: EA
Q2-Q7 = SQJ858AEP-T1-GE3: MOSFET, N-CH, 40 V, 58 A, PowerPAK_SO-8L; Manufacturer: Vishay-Siliconix; Alternate Manufacturer: None; SymbolCreator: a0412235; U/M: EA; ChType: N; Value: 40V; VdsMax_V: 40; Value1: 0.0075 ohm; Rdson45_ohm: 0.0075; Value2: 36 nC; QgTyp_nC: 36; Vgs_V: 20; IdsMax_A: 58; AEC Category: Q101
Q8 = SQJ422EP-T1-GE3: MOSFET, N-CH, 40 V, 75 A, PowerPAK_SO-8L; Manufacturer: Vishay-Siliconix; Alternate Manufacturer: None; SymbolCreator: a0412235; U/M: EA; ChType: N; Value: 40V; VdsMax_V: 40; Value1: 0.0043 ohm; Rdson45_ohm: 0.0043; Value2: 67 nC; QgTyp_nC: 67; Vgs_V: 20; IdsMax_A: 75; AEC Category: Q101
R1 R2 R14 R19 R21 R24 R29 = CRCW040210K0JNED: RES, 10 k, 5%, 0.063 W, 0402; Manufacturer: Vishay-Dale; CompType: Resistor; Value: 10k; Res_ohm: 10000; Value_Code: 10k0; Tolerance_%: 5; Power_W: 0.063; Value2: 0.063W; VDC_V: 50; TempCo: 200 ppm/C; EIA_Code: E24; U/M: EA; AEC Category: Q200
R3-R5 = PMR100HZPFU7L00: RES SMD 0.007 OHM 1% 3W 2512; Manufacturer: Bourns Inc.; CompType: Resistor; Value: 0.007; Value_Code: 7L000; Tolerance_%: 1; Power_W: 3; TempCo: 100 ppm/C; EIA_Code: E96; U/M: EA
R6-R9 = CRCW040225K5FKED: RES, 25.5 k, 1%, 0.063 W, 0402; Manufacturer: Vishay-Dale; CompType: Resistor; Value: 25.5k; Res_ohm: 25500; Value_Code: 25k5; Tolerance_%: 1; Power_W: 0.063; Value2: 0.063W; VDC_V: 50; TempCo: 100 ppm/C; EIA_Code: E96; U/M: EA; AEC Category: Q200
R10-R13 = CRCW04024K99FKED: RES, 4.99 k, 1%, 0.063 W, 0402; Manufacturer: Vishay-Dale; CompType: Resistor; Value: 4.99k; Res_ohm: 4990; Value_Code: 4k99; Tolerance_%: 1; Power_W: 0.063; Value2: 0.063W; VDC_V: 50; TempCo: 100 ppm/C; EIA_Code: E96; U/M: EA; AEC Category: Q200
R15 = ERJ-2GE0R00X: RES, 0, 5%, 0.063 W, 0402; Manufacturer: Panasonic; CompType: Resistor; Value: 0; Value_Code: 0000; Tolerance_%: 5; Power_W: 0.063; Value2: 0.063W; VDC_V: 50; TempCo: 600 ppm/C; EIA_Code: E24; U/M: EA; AEC Category: Q200
R16-R18 = CRCW04021K00JNED: RES, 1.0 k, 5%, 0.063 W, 0402; Manufacturer: Vishay-Dale; CompType: Resistor; Value: 1.0k; Res_ohm: 1000; Value_Code: 1k00; Tolerance_%: 5; Power_W: 0.063; Value2: 0.063W; VDC_V: 50; TempCo: 200 ppm/C; EIA_Code: E24; U/M: EA; AEC Category: Q200
R20 = CRCW0402100RFKED: RES, 100, 1%, 0.063 W, 0402; Manufacturer: Vishay-Dale; CompType: Resistor; Value: 100; Value_Code: 100R; Tolerance_%: 1; Power_W: 0.063; Value2: 0.063W; VDC_V: 50; TempCo: 100 ppm/C; EIA_Code: E96; U/M: EA; AEC Category: Q200
R22 R23 R25 = CRCW040256R0JNED: RES, 56, 5%, 0.063 W, 0402; Manufacturer: Vishay-Dale; CompType: Resistor; Value: 56; Value_Code: 56R0; Tolerance_%: 5; Power_W: 0.063; Value2: 0.063W; VDC_V: 50; TempCo: 200 ppm/C; EIA_Code: E24; U/M: EA; AEC Category: Q200
R26-R28 = CRCW040215K0JNED: RES, 15 k, 5%, 0.063 W, 0402; Manufacturer: Vishay-Dale; CompType: Resistor; Value: 15k; Res_ohm: 15000; Value_Code: 15k0; Tolerance_%: 5; Power_W: 0.063; Value2: 0.063W; VDC_V: 50; TempCo: 200 ppm/C; EIA_Code: E24; U/M: EA; AEC Category: Q200
R30 R31 = CRCW0402330RJNED: RES, 330, 5%, 0.063 W, 0402; Manufacturer: Vishay-Dale; CompType: Resistor; Value: 330; Value_Code: 330R; Tolerance_%: 5; Power_W: 0.063; Value2: 0.063W; VDC_V: 50; TempCo: 200 ppm/C; EIA_Code: E24; U/M: EA; AEC Category: Q200
TP1 TP3 = 5006: Test Point, Compact, Black, TH; Manufacturer: Keystone; CompType: Test Point Loop; U/M: EA
TP2 = 5005: Test Point, Compact, Red, TH; Manufacturer: Keystone; CompType: Test Point Loop; U/M: EA
U2 = LMT86QDCKRQ1: SC70 Analog Temperature Sensor with Class-AB Output, DCK0005A; Alternate PartNumber: LMT86QDCKTQ1; Manufacturer: Texas Instruments; SymbolCreator: a0799628; CompType: IC; U/M: EA
U3 = DRV83053EPHPRQ1: Three Phase Automotive Gate Driver with Three Integrated Current Shunt Amplifiers and Voltage Regulator, PHP0048G; Alternate PartNumber: DRV83053EPHPQ1; Manufacturer: Texas Instruments; SymbolCreator: Altium; CompType: IC; U/M: EA
U4 = LM53600NQDSXRQ1: Synchronous Buck Regulator for 650mA Space Constraint Applications, DSX0010A; Manufacturer: Texas Instruments; SymbolCreator: Altium; CompType: IC; U/M: EA

## Sheet TID_Hardware.SchDoc
size 431 x 279 mm; Date: Not shown in title block; ApprovedBy: Not shown in title block; CheckedBy: Not shown in title block; Author: Not shown in title block; CompanyName: Not shown in title block; Engineer: Not shown in title block; Organization: Not shown in title block; Address1: Not shown in title block; Address2: Not shown in title block; Address3: Not shown in title block; Address4: Not shown in title block; DocumentNumber: 1; Revision: Use project parameter SCH_Rev; SheetNumber: 3; SheetTotal: 3; PageSetup: Record=PageOptions¦CenterHorizontal=True¦CenterVertical=True¦PrintScale=1.00¦XCorrection=1.00¦YCorrection=1.00¦PrintKind=0¦BorderSize=5000000¦LeftOffset=0¦BottomOffset=0¦Orientation=2¦PaperLength=1000¦PaperWidth=1000¦Scale=100¦PaperSource=15¦PrintQuality=600¦MediaType=1¦DitherType=10¦PaperKind=Letter¦PrintScaleMode=1
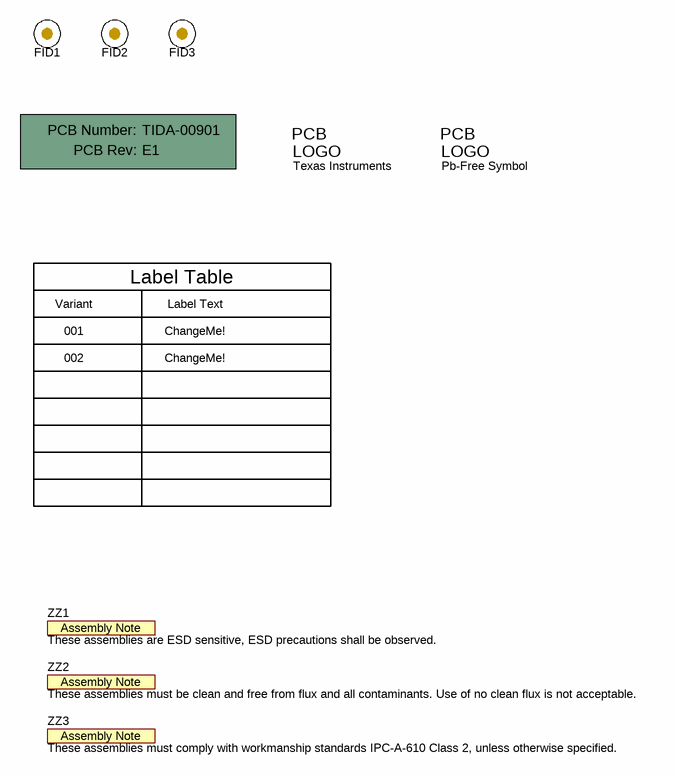
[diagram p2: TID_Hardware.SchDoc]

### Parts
!PCB1  Printed Circuit Board  (value not drawn)  (mechanical)
FID1  Fiducial  [Fiducial10-20]  (value not drawn)
FID2  Fiducial  [Fiducial10-20]  (value not drawn)
FID3  Fiducial  [Fiducial10-20]  (value not drawn)
Logo1  Texas Instruments  [TI_Stacked_Overlay_Small]  (no BOM)
Logo2  Pb-Free Symbol  [Pb-Free_Overlay_Small]  (no BOM)
ZZ1  These assemblies are ESD sensitive, ESD precautions shall be observed.  [AssemblyNote]  (no BOM)
ZZ2  These assemblies must be clean and free from flux and all contaminants. Use of no clean flux is not acceptable.  [AssemblyNote]  (no BOM)
ZZ3  These assemblies must comply with workmanship standards IPC-A-610 Class 2, unless otherwise specified.  [AssemblyNote]  (no BOM)

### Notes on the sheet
- Variant
- Label Table
- Label Text
- 001
- 002
- ChangeMe!

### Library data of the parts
!PCB1 = PCB: Manufacturer: Any; PartNumber: TIDA-00901; SymbolCreator: a0412235
FID1-FID3 = Fiducial: Fiducial mark.  There is nothing to buy or mount.; SymbolCreator: codlsc
Logo1 = TI_Logo: Texas Instrument Corporate Signature; SymbolCreator: codlsc
Logo2 = Pb-Free: SymbolCreator: a0412235
ZZ1-ZZ3 = AssemblyNote: SymbolCreator: codlsc

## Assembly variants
001: not fitted FID1 FID2 FID3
